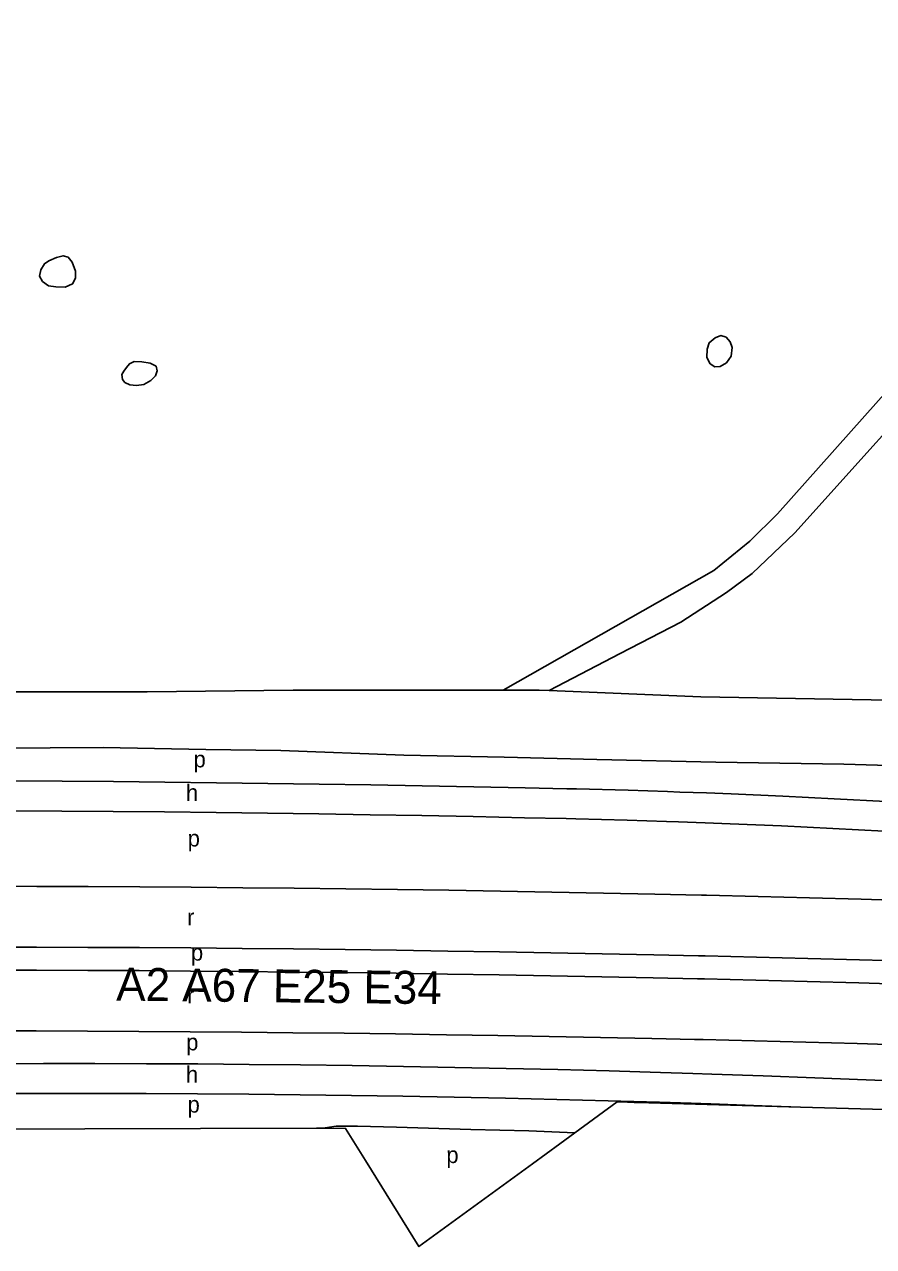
# Model space of a CAD drawing. Extents: x 160204 to 161526, y 379528 to 381793.
# Drawn here: x 160569.9 to 160776.3, y 379547.5 to 379844.6 of the extents above; entities that cross this region are included whole.
import ezdxf

# ---------------------------------------------------------------- set-up
doc = ezdxf.new("R2010")
doc.units = 0
for name, color, linetype in [('BLT_Basislijn', 7, 'Continuous'), ('BLT_Centroide', 7, 'Continuous'), ('BLT_Gemeentegrens', 7, 'Continuous'), ('BLT_Straatnaam_hoofdweg', 7, 'Continuous')]:
    doc.layers.add(name, color=color, linetype=linetype)

msp = doc.modelspace()

# ---------------------------------------------------------------- linework, layer by layer
at = {"layer": 'BLT_Basislijn'}
for points in [[(160686.29, 379682.82), (160737.48, 379711.91), (160746.25, 379719.03), (160752.91, 379725.65), (160794.74, 379772.59), (160811.69, 379792.71), (160828.15, 379812.23), (160847.28, 379835.89), (160857.41, 379844.61)], [(160714.73, 379691.69), (160729.47, 379699.34), (160740.52, 379706.54), (160746.8, 379711.17), (160757.2, 379721.03), (160797.44, 379765.72), (160850.78, 379831.75), (160856.96, 379837.67), (160862.11, 379841.36)], [(160697.47, 379682.72), (160714.73, 379691.69)], [(160686.29, 379682.82), (160659.38, 379682.82), (160635.25, 379682.82), (160599.72, 379682.37), (160559.85, 379682.37), (160519.83, 379681.92), (160461.08, 379680.72), (160401.57, 379679.97), (160323.63, 379679.37), (160269.97, 379679.22), (160252.88, 379679.67), (160246.89, 379680.87), (160241.96, 379683.92)], [(160697.47, 379682.72), (160695.05, 379682.82), (160686.29, 379682.82)], [(160962.04, 379674.37), (160928.58, 379676.98), (160898.9, 379677.88), (160865.48, 379678.32), (160810.17, 379679.97), (160775.69, 379680.42), (160734.32, 379681.17), (160697.47, 379682.72)], [(160563.17, 379668.7), (160589.01, 379668.81), (160613.98, 379668.38), (160632.18, 379668.08), (160662.14, 379666.95), (160686.53, 379666.48), (160709.05, 379665.91), (160737.95, 379665.26), (160769.1, 379664.77), (160820.86, 379663.28), (160849.87, 379662.62), (160902.88, 379661.28), (160918.99, 379661), (160935.1, 379660.15), (160946.02, 379659.49), (160953.84, 379659.12), (160958.98, 379658.56), (160962.1, 379657.7), (160964.74, 379656.63), (160967.7, 379654.85), (160969.48, 379653.29), (160970.5, 379651.89), (160971.63, 379650.06), (160972.17, 379648.23)], [(160735.68, 379657.79), (160729.18, 379658.03), (160726.21, 379658.14), (160716.64, 379658.44), (160704.11, 379658.77), (160701.7, 379658.82), (160691.6, 379659.04), (160679.09, 379659.3), (160666.58, 379659.53), (160654.07, 379659.75), (160641.56, 379659.95), (160629.05, 379660.13), (160616.55, 379660.29), (160604.04, 379660.43), (160591.53, 379660.55), (160579.02, 379660.66), (160566.51, 379660.74)], [(160963.12, 379642.17), (160953.74, 379642.63), (160941.3, 379643.32), (160928.86, 379644.08), (160916.43, 379644.91), (160904, 379645.81), (160891.57, 379646.79), (160879.16, 379647.83), (160866.75, 379648.94), (160861.29, 379649.45), (160854.29, 379650.11), (160849.51, 379650.54), (160841.81, 379651.22), (160829.31, 379652.26), (160816.81, 379653.23), (160804.3, 379654.13), (160791.79, 379654.96), (160779.28, 379655.72), (160766.76, 379656.4), (160754.23, 379657.02), (160741.71, 379657.56), (160735.68, 379657.79)], [(160735.33, 379650.55), (160728.92, 379650.79), (160725.97, 379650.89), (160716.43, 379651.19), (160703.94, 379651.52), (160701.54, 379651.57), (160691.44, 379651.79), (160678.95, 379652.05), (160666.45, 379652.28), (160653.95, 379652.5), (160641.45, 379652.7), (160628.96, 379652.88), (160616.46, 379653.04), (160603.96, 379653.18), (160591.46, 379653.3), (160578.96, 379653.41), (160566.46, 379653.49)], [(160963.12, 379634.9), (160961.89, 379634.95), (160953.36, 379635.39), (160940.88, 379636.08), (160928.4, 379636.84), (160915.92, 379637.68), (160903.45, 379638.58), (160890.99, 379639.56), (160878.53, 379640.61), (160866.08, 379641.72), (160860.61, 379642.24), (160853.63, 379642.89), (160848.86, 379643.32), (160841.18, 379644), (160828.73, 379645.04), (160816.27, 379646), (160803.8, 379646.9), (160791.33, 379647.73), (160778.86, 379648.48), (160766.38, 379649.16), (160753.9, 379649.78), (160741.41, 379650.32), (160735.33, 379650.55)], [(160560.33, 379635.1), (160572.86, 379635.07), (160585.38, 379635.02), (160597.91, 379634.95), (160610.44, 379634.86), (160622.96, 379634.75), (160635.49, 379634.62), (160648.02, 379634.48), (160660.54, 379634.31), (160673.07, 379634.13), (160685.59, 379633.92), (160698.12, 379633.7), (160710.64, 379633.46), (160723.17, 379633.2), (160734.47, 379632.95)], [(160734.47, 379632.95), (160735.69, 379632.92), (160748.21, 379632.62), (160760.73, 379632.3), (160773.26, 379631.97), (160785.78, 379631.61)], [(160560.31, 379620.35), (160572.81, 379620.32), (160585.31, 379620.27), (160597.82, 379620.2), (160610.32, 379620.11), (160622.83, 379620), (160635.33, 379619.87), (160647.83, 379619.73), (160660.34, 379619.56), (160672.84, 379619.38), (160685.34, 379619.18), (160697.84, 379618.95), (160710.35, 379618.71), (160722.85, 379618.45), (160733.75, 379618.21)], [(160733.75, 379618.21), (160735.35, 379618.17), (160747.85, 379617.88), (160760.35, 379617.56), (160772.85, 379617.22), (160785.35, 379616.87)], [(160560.3, 379614.75), (160572.79, 379614.72), (160585.29, 379614.67), (160597.78, 379614.6), (160610.28, 379614.51), (160622.77, 379614.4), (160635.27, 379614.27), (160647.76, 379614.13), (160660.26, 379613.96), (160672.75, 379613.78), (160685.25, 379613.58), (160697.74, 379613.35), (160710.23, 379613.11), (160722.73, 379612.85), (160733.48, 379612.61)], [(160733.48, 379612.61), (160735.22, 379612.58), (160747.71, 379612.28), (160760.2, 379611.96), (160772.69, 379611.62), (160785.18, 379611.27)], [(160732.76, 379597.88), (160722.41, 379598.11), (160709.94, 379598.37), (160697.47, 379598.61), (160685, 379598.83), (160672.52, 379599.03), (160660.05, 379599.21), (160647.58, 379599.38), (160635.11, 379599.52), (160622.64, 379599.65), (160610.16, 379599.76), (160597.69, 379599.85), (160585.22, 379599.92), (160572.74, 379599.97), (160560.27, 379600)], [(160784.75, 379596.52), (160772.29, 379596.88), (160759.82, 379597.21), (160747.35, 379597.53), (160734.88, 379597.83), (160732.76, 379597.88)], [(160562.02, 379591.99), (160574.52, 379592.02), (160587.02, 379592.02), (160599.53, 379591.99), (160612.03, 379591.92), (160624.53, 379591.83), (160637.03, 379591.69), (160649.53, 379591.53), (160662.03, 379591.33), (160674.53, 379591.1), (160687.03, 379590.84), (160699.52, 379590.54), (160712.02, 379590.21), (160724.52, 379589.85), (160732.36, 379589.6)], [(160732.36, 379589.6), (160737.01, 379589.46), (160749.5, 379589.03), (160762, 379588.57), (160774.49, 379588.07), (160786.98, 379587.55)], [(160562.05, 379584.74), (160574.53, 379584.77), (160587.02, 379584.77), (160599.5, 379584.74), (160611.98, 379584.67), (160624.46, 379584.58), (160636.94, 379584.44), (160649.42, 379584.28), (160661.9, 379584.08), (160674.38, 379583.85), (160686.86, 379583.59), (160699.34, 379583.29), (160711.82, 379582.97), (160724.3, 379582.6), (160732, 379582.36)], [(160732, 379582.36), (160736.77, 379582.21), (160749.25, 379581.78), (160758.54, 379581.44)], [(160703.7, 379575.21), (160692.48, 379575.63), (160678.38, 379576.01), (160660.33, 379576.55), (160650.86, 379576.82), (160645.69, 379576.82), (160642.95, 379576.39), (160642.65, 379576.29)]]:
    msp.add_lwpolyline(points, dxfattribs=at)
for points in [[(160575.81, 379787.14), (160577.64, 379787.99), (160579.27, 379788.38), (160580.51, 379788.07), (160581.48, 379786.79), (160582.33, 379784.65), (160582.33, 379782.95), (160581.6, 379781.55), (160579.77, 379780.73), (160577.48, 379780.85), (160575.73, 379781.08), (160574.26, 379782.13), (160573.56, 379783.41), (160573.87, 379784.97), (160574.76, 379786.44)], [(160737.78, 379768.44), (160736.31, 379767.22), (160735.82, 379765.66), (160735.78, 379763.62), (160736.56, 379762.15), (160737.7, 379761.37), (160739.01, 379761.49), (160740.52, 379762.35), (160741.7, 379763.95), (160741.91, 379766.11), (160741.46, 379767.42), (160740.44, 379768.56), (160739.21, 379768.97)], [(160594.72, 379761.21), (160595.41, 379762.1), (160596.58, 379762.68), (160598.4, 379762.57), (160600.46, 379762.26), (160601.9, 379761.52), (160602.13, 379760.43), (160601.78, 379759.23), (160600.62, 379758.07), (160598.87, 379757.1), (160597.16, 379756.82), (160595.49, 379756.98), (160594.29, 379757.56), (160593.71, 379758.3), (160593.55, 379759.5), (160594.02, 379760.36)]]:
    msp.add_lwpolyline(points, close=True, dxfattribs=at)
at = {"layer": 'BLT_Gemeentegrens'}
msp.add_line((160718.13, 379582.56), (160718.17, 379582.58), dxfattribs=at)
for points in [[(160703.7, 379575.21), (160713.97, 379582.7), (160716.49, 379582.63), (160718.13, 379582.56), (160718.17, 379582.58), (160718.85, 379582.56), (160758.54, 379581.44)], [(160758.54, 379581.44), (160840.25, 379579.13), (160840.69, 379577.74)], [(160282.09, 379562.78), (160296.67, 379572.82), (160400, 379575.68), (160500, 379575.91), (160640.86, 379576.3), (160642.65, 379576.29)], [(160642.65, 379576.29), (160647.94, 379576.26), (160652.81, 379568.42), (160665.76, 379547.53), (160693.37, 379567.67), (160700, 379572.51), (160703.7, 379575.21)]]:
    msp.add_lwpolyline(points, dxfattribs=at)

# ---------------------------------------------------------------- texts
at = {"layer": 'BLT_Centroide'}
for s, p in [('p', (160610.99, 379664.02)), ('h', (160609.15, 379655.86)), ('p', (160609.57, 379644.78)), ('r', (160609.42, 379625.62)), ('p', (160610.36, 379617.04)), ('r', (160609.42, 379606.64)), ('p', (160609.2, 379595.23)), ('h', (160609.15, 379587.39)), ('p', (160609.54, 379580.09)), ('p', (160672.45, 379567.83))]:
    msp.add_text(s, height=4, dxfattribs=at).set_placement(p)
at = {"layer": 'BLT_Straatnaam_hoofdweg'}
msp.add_text('A2 A67 E25 E34', height=8, rotation=359.3536, dxfattribs=at).set_placement((160592.18, 379607.34))

doc.saveas('drawing.dxf')
